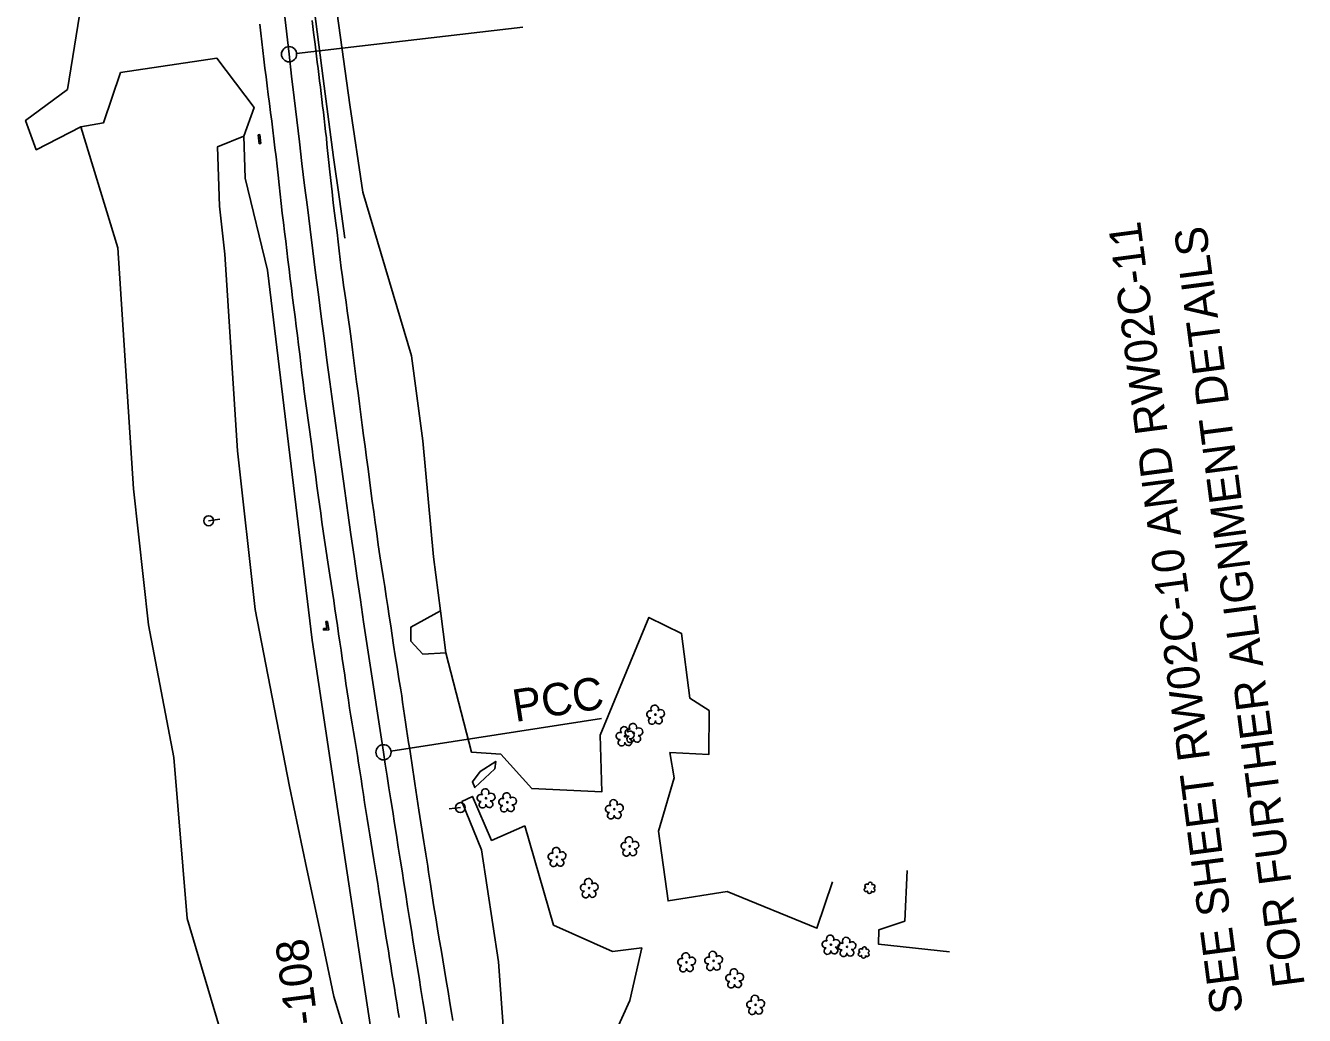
# Model space of a CAD drawing. Extents: x 477009 to 479892, y 492858 to 496862.
# Drawn here: x 478164 to 478797, y 495561 to 496051 of the extents above; entities that cross this region are included whole.
import ezdxf

# ---------------------------------------------------------------- set-up
doc = ezdxf.new("R2010")
doc.units = 0
for name, color, linetype in [('CTL Secondary Horizontal and Vertical Text', 7, 'Continuous'), ('CTL Sheet Notes CELL', 7, 'Continuous'), ('Exist Guardrail', 7, 'Continuous'), ('Exist Horizontal Alignment', 7, 'Continuous'), ('Exist Other Culture Area Outline', 7, 'Continuous'), ('Exist Roads EOP', 7, 'Continuous'), ('Exist Structure Minor Head and End Wall', 7, 'Continuous'), ('Exist Utilities Power Pole CELL', 7, 'Continuous'), ('Exist Vegetation Hedge Row', 7, 'Continuous'), ('Exist Vegetation Shrub CELL', 7, 'Continuous'), ('Exist Vegetation Tree CELL', 7, 'Continuous'), ('Exist Vegetation Woods Line', 7, 'Continuous')]:
    doc.layers.add(name, color=color, linetype=linetype)

msp = doc.modelspace()

# ---------------------------------------------------------------- linework, layer by layer
at = {"layer": 'Exist Guardrail'}
msp.add_lwpolyline([(478296.25, 496146.09), (478300.41, 496111.06), (478306.15, 496064.49), (478311.22, 496024.56), (478316.39, 495985.44), (478319.3, 495964.86), (478322.01, 495945.56)], dxfattribs=at)
at = {"layer": 'Exist Horizontal Alignment'}
for p, q in [((478294.37, 496036.52), (478241.07, 496499.45)), ((478298.1, 496036.95), (478410.08, 496049.85)), ((478344.79, 495691.84), (478448.96, 495708.04))]:
    msp.add_line(p, q, dxfattribs=at)
for centre in [(478294.37, 496036.52), (478341.08, 495691.26)]:
    msp.add_circle(centre, 3.75, dxfattribs=at)
for centre, radius, start, end in [((487025.09, 497041.83), 8788.41, 186.568463, 188.840055), ((501490.44, 499291.54), 23427.66, 188.840055, 189.304896)]:
    msp.add_arc(centre, radius, start, end, dxfattribs=at)
at = {"layer": 'Exist Other Culture Area Outline'}
msp.add_lwpolyline([(478396.12, 495683), (478386.32, 495673.78), (478385.07, 495676.63), (478388.96, 495681.75), (478396.64, 495686.77), (478396.12, 495683)], dxfattribs=at)
at = {"layer": 'Exist Roads EOP'}
for points in [[(478348.79, 495560.12), (478348.22, 495563.76), (478347.65, 495567.38), (478347.06, 495570.98), (478346.48, 495574.58), (478345.88, 495578.21), (478345.29, 495581.89), (478344.69, 495585.59), (478344.09, 495589.3), (478343.5, 495592.97), (478342.91, 495596.62), (478342.33, 495600.23), (478341.75, 495603.84), (478341.17, 495607.48), (478340.59, 495611.16), (478340.01, 495614.88), (478339.43, 495618.64), (478338.84, 495622.44), (478338.23, 495626.29), (478337.63, 495630.18), (478337.01, 495634.12), (478336.37, 495638.11), (478335.71, 495642.16), (478335.04, 495646.26), (478334.36, 495650.37), (478333.69, 495654.45), (478333.04, 495658.49), (478332.39, 495662.5), (478331.76, 495666.48), (478331.15, 495670.41), (478330.56, 495674.3), (478329.98, 495678.16), (478329.4, 495682), (478328.8, 495685.86), (478328.17, 495689.74), (478327.52, 495693.63), (478326.87, 495697.53), (478326.22, 495701.43), (478325.59, 495705.31), (478324.97, 495709.19), (478324.35, 495713.1), (478323.74, 495717.07), (478323.13, 495721.11), (478322.52, 495725.2), (478321.92, 495729.33), (478321.32, 495733.45), (478320.71, 495737.56), (478320.11, 495741.68), (478319.51, 495745.78), (478318.91, 495749.88), (478318.31, 495753.97), (478317.7, 495758.06), (478317.09, 495762.16), (478316.47, 495766.3), (478315.85, 495770.47), (478315.22, 495774.68), (478314.58, 495778.93), (478313.94, 495783.2), (478313.29, 495787.51), (478312.64, 495791.86), (478311.98, 495796.24), (478311.33, 495800.64), (478310.67, 495805.07), (478310.02, 495809.52), (478309.37, 495814), (478308.75, 495818.49), (478308.15, 495823), (478307.57, 495827.53), (478306.99, 495832.09), (478306.38, 495836.71), (478305.75, 495841.38), (478305.09, 495846.11), (478304.43, 495850.85), (478303.78, 495855.58), (478303.14, 495860.29), (478302.51, 495864.98), (478301.9, 495869.65), (478301.31, 495874.3), (478300.74, 495878.93), (478300.19, 495883.53), (478299.64, 495888.13), (478299.08, 495892.73), (478298.51, 495897.35), (478297.92, 495901.98), (478297.32, 495906.63), (478296.73, 495911.31), (478296.14, 495916.01), (478295.56, 495920.74), (478294.98, 495925.46), (478294.4, 495930.14), (478293.83, 495934.79), (478293.26, 495939.4), (478292.7, 495944), (478292.14, 495948.63), (478291.59, 495953.28), (478291.03, 495957.97), (478290.49, 495962.66), (478289.96, 495967.33), (478289.45, 495971.99), (478288.94, 495976.64), (478288.44, 495981.24), (478287.93, 495985.78), (478287.41, 495990.25), (478286.88, 495994.66), (478286.34, 495999.03), (478285.79, 496003.41), (478285.24, 496007.78), (478284.67, 496012.16), (478284.1, 496016.54), (478283.55, 496020.91), (478282.99, 496025.28), (478282.45, 496029.65), (478281.92, 496034.01), (478281.39, 496038.35), (478280.88, 496042.69), (478280.38, 496047.01), (478279.88, 496051.32)], [(478305.83, 496053.24), (478306.54, 496047.29), (478307.25, 496041.43), (478307.97, 496035.53), (478308.34, 496032.53), (478308.72, 496029.5), (478309.1, 496026.43), (478309.48, 496023.34), (478309.86, 496020.25), (478310.23, 496017.17), (478310.6, 496014.09), (478310.98, 496011), (478311.35, 496007.88), (478311.73, 496004.71), (478312.1, 496001.52), (478312.47, 495998.33), (478312.82, 495995.17), (478313.14, 495992.06), (478313.45, 495988.98), (478313.75, 495985.94), (478314.06, 495982.92), (478314.38, 495979.92), (478315.04, 495974.03), (478315.67, 495968.4), (478316.27, 495963.04), (478316.89, 495957.92), (478317.52, 495953.01), (478318.11, 495948.29), (478318.65, 495943.74), (478319.18, 495939.32), (478319.7, 495935.02), (478320.24, 495930.72), (478320.81, 495926.42), (478321.38, 495922.22), (478321.96, 495918.1), (478322.56, 495913.88), (478323.16, 495909.53), (478323.76, 495905.15), (478324.38, 495900.7), (478325.03, 495895.77), (478325.72, 495890.38), (478326.42, 495885.04), (478327.12, 495879.81), (478327.81, 495874.47), (478328.49, 495869.01), (478329.19, 495863.62), (478329.9, 495858.34), (478330.6, 495853.1), (478331.27, 495847.86), (478331.98, 495842.48), (478332.72, 495836.97), (478333.45, 495831.47), (478334.17, 495826), (478334.87, 495820.64), (478335.57, 495815.39), (478336.27, 495810.14), (478336.97, 495804.85), (478337.73, 495799.41), (478338.53, 495793.85), (478339.35, 495788.48), (478340.16, 495783.33), (478340.95, 495778.23), (478341.72, 495773.18), (478342.47, 495768.24), (478343.22, 495763.42), (478343.97, 495758.62), (478344.7, 495753.81), (478345.41, 495749.03), (478346.1, 495744.2), (478346.91, 495738.94), (478347.83, 495733.27), (478348.74, 495727.64), (478349.64, 495722.07), (478350.1, 495719.1), (478350.58, 495715.99), (478351.07, 495712.74), (478351.56, 495709.41), (478352.06, 495706.09), (478352.55, 495702.75), (478353.05, 495699.42), (478353.55, 495696.08), (478354.06, 495692.73), (478354.58, 495689.37), (478355.11, 495685.99), (478355.64, 495682.61), (478356.16, 495679.24), (478356.67, 495675.88), (478357.16, 495672.54), (478357.65, 495669.21), (478358.14, 495665.93), (478358.62, 495662.68), (478359.11, 495659.47), (478359.59, 495656.3), (478360.08, 495653.16), (478360.56, 495650.06), (478361.05, 495647), (478361.54, 495643.96), (478362.03, 495640.92), (478362.5, 495637.89), (478362.97, 495634.87), (478363.44, 495631.87), (478364.34, 495626.01), (478365.2, 495620.32), (478366.08, 495614.75), (478366.97, 495609.31), (478367.85, 495604), (478368.73, 495598.83), (478369.61, 495593.68), (478370.49, 495588.54), (478371.33, 495583.44), (478372.16, 495578.33), (478373.04, 495572.96), (478374, 495567.3), (478374.95, 495561.47), (478375.43, 495558.51)]]:
    msp.add_lwpolyline(points, dxfattribs=at)
at = {"layer": 'Exist Structure Minor Head and End Wall'}
for p, q in [((478279.11, 495996.74), (478279.94, 495996.82)), ((478280.41, 495992.35), (478279.94, 495996.82)), ((478279.59, 495992.26), (478279.11, 495996.74)), ((478279.59, 495992.26), (478280.41, 495992.35)), ((478311.44, 495751.57), (478311.38, 495752.4)), ((478312.58, 495755.89), (478313.4, 495756.02))]:
    msp.add_line(p, q, dxfattribs=at)
for points in [[(478311.38, 495752.4), (478313.09, 495752.53), (478312.58, 495755.89)], [(478311.44, 495751.57), (478314.04, 495751.76), (478313.4, 495756.02)]]:
    msp.add_lwpolyline(points, dxfattribs=at)
at = {"layer": 'Exist Utilities Power Pole CELL'}
for p, q in [((478254.57, 495805.76), (478260.12, 495806.63)), ((478254.57, 495805.76), (478254.57, 495805.76)), ((478379.15, 495663.89), (478373.56, 495663.22)), ((478379.15, 495663.89), (478379.15, 495663.89))]:
    msp.add_line(p, q, dxfattribs=at)
for centre in [(478254.57, 495805.76), (478379.15, 495663.89)]:
    msp.add_circle(centre, 2.45, dxfattribs=at)
at = {"layer": 'Exist Vegetation Hedge Row'}
for points in [[(478191.35, 496000.56), (478202.57, 496002.62), (478210.99, 496027.47), (478258.71, 496034.57), (478277.12, 496010.2), (478272.01, 495995.92)], [(478371.87, 495740.52), (478360.53, 495739.79), (478354.66, 495746.21), (478354.65, 495753.18), (478369.24, 495761.19)]]:
    msp.add_lwpolyline(points, dxfattribs=at)
at = {"layer": 'Exist Vegetation Shrub CELL'}
for p, q in [((478581.71, 495624), (478581.71, 495624)), ((478578.81, 495592.05), (478578.81, 495592.05))]:
    msp.add_line(p, q, dxfattribs=at)
for centre, radius, start, end in [((478579.91, 495623.29), 0.955, 95.10992, 327.95341), ((478580.23, 495625.13), 0.968, 35.89076, 245.42165), ((478581.94, 495626.04), 0.99, 334.83907, 200.47174), ((478583.35, 495623.07), 0.937, 204.99133, 73.46012), ((478583.38, 495624.87), 0.929, 284.45672, 126.08612), ((478581.58, 495622.31), 0.984, 151.27966, 21.38702), ((478577.01, 495591.35), 0.955, 95.10992, 327.95341), ((478577.33, 495593.18), 0.968, 35.89076, 245.42165), ((478579.04, 495594.09), 0.99, 334.83907, 200.47174), ((478580.45, 495591.12), 0.937, 204.99133, 73.46012), ((478580.49, 495592.92), 0.929, 284.45672, 126.08612), ((478578.69, 495590.37), 0.984, 151.27966, 21.38702)]:
    msp.add_arc(centre, radius, start, end, dxfattribs=at)
at = {"layer": 'Exist Vegetation Tree CELL'}
for p, q in [((478475.67, 495709.88), (478475.67, 495709.88)), ((478464.94, 495700.82), (478464.94, 495700.82)), ((478460.63, 495699.2), (478460.63, 495699.2)), ((478391.84, 495668.49), (478391.84, 495668.49)), ((478402.43, 495666.53), (478402.43, 495666.53)), ((478455.34, 495663.1), (478455.34, 495663.1)), ((478462.96, 495644.7), (478462.96, 495644.7)), ((478426.93, 495639.51), (478426.93, 495639.51)), ((478442.87, 495624.08), (478442.87, 495624.08)), ((478562.52, 495596.09), (478562.52, 495596.09)), ((478570.46, 495595.02), (478570.46, 495595.02)), ((478491.05, 495587.4), (478491.05, 495587.4)), ((478504.44, 495588.09), (478504.44, 495588.09)), ((478514.88, 495579.45), (478514.88, 495579.45)), ((478525.25, 495566.33), (478525.25, 495566.33))]:
    msp.add_line(p, q, dxfattribs=at)
for centre in [(478475.67, 495709.88), (478460.63, 495699.2), (478464.94, 495700.82), (478391.84, 495668.49), (478402.43, 495666.53), (478455.34, 495663.1), (478462.96, 495644.7), (478426.93, 495639.51), (478442.87, 495624.08), (478562.52, 495596.09), (478570.46, 495595.02), (478491.05, 495587.4), (478504.44, 495588.09), (478514.88, 495579.45), (478525.25, 495566.33)]:
    msp.add_circle(centre, 0.326, dxfattribs=at)
for centre, radius, start, end in [((478475.29, 495712.75), 1.86, 330.16508, 219.71335), ((478478.22, 495710.47), 1.9, 257.1011, 134.19993), ((478473.07, 495710.03), 1.73, 62.66361, 279.3457), ((478473.97, 495706.76), 1.69, 111.56708, 6.23104), ((478477.35, 495706.98), 1.7, 181.28216, 74.55999), ((478458.02, 495699.35), 1.73, 62.66361, 279.3457), ((478460.24, 495702.07), 1.86, 330.16508, 219.71335), ((478462.33, 495700.97), 1.73, 62.66361, 279.3457), ((478463.18, 495699.79), 1.9, 257.1011, 134.19993), ((478464.56, 495703.69), 1.86, 330.16508, 219.71335), ((478466.61, 495697.92), 1.7, 181.28216, 74.55999), ((478467.49, 495701.4), 1.9, 257.1011, 134.19993), ((478458.93, 495696.08), 1.69, 111.56708, 6.23104), ((478462.3, 495696.3), 1.7, 181.28216, 74.55999), ((478463.24, 495697.7), 1.69, 111.56708, 6.23104), ((478389.23, 495668.64), 1.73, 62.66361, 279.3457), ((478391.45, 495671.36), 1.86, 330.16508, 219.71335), ((478394.39, 495669.08), 1.9, 257.1011, 134.19993), ((478399.82, 495666.68), 1.73, 62.66361, 279.3457), ((478402.04, 495669.4), 1.86, 330.16508, 219.71335), ((478404.98, 495667.12), 1.9, 257.1011, 134.19993), ((478454.96, 495665.97), 1.86, 330.16508, 219.71335), ((478390.14, 495665.37), 1.69, 111.56708, 6.23104), ((478393.51, 495665.59), 1.7, 181.28216, 74.55999), ((478400.72, 495663.41), 1.69, 111.56708, 6.23104), ((478404.1, 495663.63), 1.7, 181.28216, 74.55999), ((478452.74, 495663.25), 1.73, 62.66361, 279.3457), ((478453.64, 495659.98), 1.69, 111.56708, 6.23104), ((478457.01, 495660.2), 1.7, 181.28216, 74.55999), ((478457.89, 495663.69), 1.9, 257.1011, 134.19993), ((478462.57, 495647.57), 1.86, 330.16508, 219.71335), ((478426.54, 495642.38), 1.86, 330.16508, 219.71335), ((478460.35, 495644.85), 1.73, 62.66361, 279.3457), ((478461.25, 495641.58), 1.69, 111.56708, 6.23104), ((478464.63, 495641.8), 1.7, 181.28216, 74.55999), ((478465.5, 495645.29), 1.9, 257.1011, 134.19993), ((478424.32, 495639.66), 1.73, 62.66361, 279.3457), ((478425.22, 495636.39), 1.69, 111.56708, 6.23104), ((478428.6, 495636.61), 1.7, 181.28216, 74.55999), ((478429.48, 495640.1), 1.9, 257.1011, 134.19993), ((478440.26, 495624.23), 1.73, 62.66361, 279.3457), ((478442.48, 495626.95), 1.86, 330.16508, 219.71335), ((478445.42, 495624.67), 1.9, 257.1011, 134.19993), ((478441.16, 495620.96), 1.69, 111.56708, 6.23104), ((478444.54, 495621.18), 1.7, 181.28216, 74.55999), ((478562.13, 495598.96), 1.86, 330.16508, 219.71335), ((478565.06, 495596.68), 1.9, 257.1011, 134.19993), ((478570.07, 495597.89), 1.86, 330.16508, 219.71335), ((478490.67, 495590.27), 1.86, 330.16508, 219.71335), ((478504.05, 495590.96), 1.86, 330.16508, 219.71335), ((478559.91, 495596.24), 1.73, 62.66361, 279.3457), ((478560.81, 495592.97), 1.69, 111.56708, 6.23104), ((478564.19, 495593.19), 1.7, 181.28216, 74.55999), ((478567.85, 495595.17), 1.73, 62.66361, 279.3457), ((478568.75, 495591.89), 1.69, 111.56708, 6.23104), ((478572.13, 495592.12), 1.7, 181.28216, 74.55999), ((478573.01, 495595.6), 1.9, 257.1011, 134.19993), ((478488.45, 495587.56), 1.73, 62.66361, 279.3457), ((478489.35, 495584.28), 1.69, 111.56708, 6.23104), ((478492.72, 495584.5), 1.7, 181.28216, 74.55999), ((478493.6, 495587.99), 1.9, 257.1011, 134.19993), ((478501.83, 495588.24), 1.73, 62.66361, 279.3457), ((478502.73, 495584.97), 1.69, 111.56708, 6.23104), ((478506.11, 495585.19), 1.7, 181.28216, 74.55999), ((478506.99, 495588.68), 1.9, 257.1011, 134.19993), ((478512.27, 495579.61), 1.73, 62.66361, 279.3457), ((478514.49, 495582.32), 1.86, 330.16508, 219.71335), ((478517.43, 495580.04), 1.9, 257.1011, 134.19993), ((478513.18, 495576.33), 1.69, 111.56708, 6.23104), ((478516.55, 495576.55), 1.7, 181.28216, 74.55999), ((478522.65, 495566.49), 1.73, 62.66361, 279.3457), ((478524.87, 495569.21), 1.86, 330.16508, 219.71335), ((478527.8, 495566.92), 1.9, 257.1011, 134.19993), ((478523.55, 495563.21), 1.69, 111.56708, 6.23104), ((478526.93, 495563.43), 1.7, 181.28216, 74.55999)]:
    msp.add_arc(centre, radius, start, end, dxfattribs=at)
at = {"layer": 'Exist Vegetation Woods Line'}
for points in [[(478399.23, 495690.32), (478384.66, 495691.24), (478371.87, 495740.52), (478369.24, 495761.19), (478365.85, 495787.93), (478360.6, 495845.29), (478355.04, 495887.42), (478330.8, 495968.29), (478324.41, 496011.5), (478315.1, 496079.43), (478307.6, 496166.65)], [(478180.86, 496117.02), (478198.43, 496103.96), (478184.66, 496019.14), (478163.99, 496003.77), (478169.25, 495989.25), (478191.35, 496000.56)], [(478191.35, 496000.56), (478209.7, 495940.73), (478217.33, 495821.53), (478224.77, 495754.22), (478237.39, 495688.7), (478243.88, 495609.04)], [(478303.14, 495633.48), (478294.58, 495674.27), (478277.57, 495761.88), (478268.79, 495840.3), (478262.65, 495937.62), (478259.96, 495961.32), (478258.88, 495990.65), (478272.01, 495995.92)], [(478272.01, 495995.92), (478272.57, 495975.24), (478283.73, 495929.67), (478305.76, 495746.69), (478322.37, 495637.01)], [(478484.96, 495678.54), (478482.84, 495691.08), (478502.15, 495690.2), (478502.2, 495711.88), (478492.74, 495717.98), (478488.64, 495750.04), (478472.48, 495757.93), (478448.4, 495699.75), (478449.18, 495671.72), (478414.46, 495673.29), (478399.23, 495690.32)], [(478563.36, 495627.1), (478555.57, 495604.25), (478511.16, 495622.37), (478481.91, 495617.7), (478477.26, 495652.26), (478484.96, 495678.54)], [(478389.57, 495642.98), (478379.89, 495666.84), (478385.08, 495669.38), (478394.61, 495647.69), (478411.07, 495654.8)], [(478411.07, 495654.8), (478425.25, 495605.78), (478454.36, 495592.76), (478468.93, 495594.49), (478462.96, 495568.52), (478445.54, 495529.93), (478430.84, 495475.89), (478409.15, 495477.74), (478404.41, 495498.69), (478398, 495587.65), (478389.57, 495642.98)], [(478322.37, 495637.01), (478338.02, 495533.69), (478365.85, 495383.63), (478378.39, 495294.94), (478372.6, 495293.46), (478351, 495413.63), (478328.59, 495530.52), (478316.59, 495570.4), (478310.42, 495599.68), (478303.14, 495633.48)], [(478621.21, 495592.54), (478586.13, 495596.29), (478586.15, 495603.41), (478599.08, 495607.72), (478600.24, 495632.76)], [(478243.88, 495609.04), (478259.87, 495555.11), (478280.1, 495475.88), (478304.88, 495392.52), (478319.11, 495324.69), (478334.86, 495221.02), (478346.46, 495146.16), (478323.55, 495132.51), (478332.16, 495119.51)]]:
    msp.add_lwpolyline(points, dxfattribs=at)

# ---------------------------------------------------------------- texts
at = {"layer": 'CTL Secondary Horizontal and Vertical Text'}
msp.add_text('BL-108', height=16, rotation=97.12475, dxfattribs=at).set_placement((478311.9, 495531.34))
at = {"layer": 'CTL Sheet Notes CELL'}
for s, p in [('SEE SHEET RW02C-10 AND RW02C-11', (478766.49, 495562.98)), ('FOR FURTHER ALIGNMENT DETAILS', (478797.05, 495576.11))]:
    msp.add_text(s, height=16, rotation=97.41753, dxfattribs=at).set_placement(p)
at = {"layer": 'Exist Horizontal Alignment'}
msp.add_text('PCC', height=16, rotation=8.84006, dxfattribs=at).set_placement((478406.29, 495706.18))

doc.saveas('drawing.dxf')
